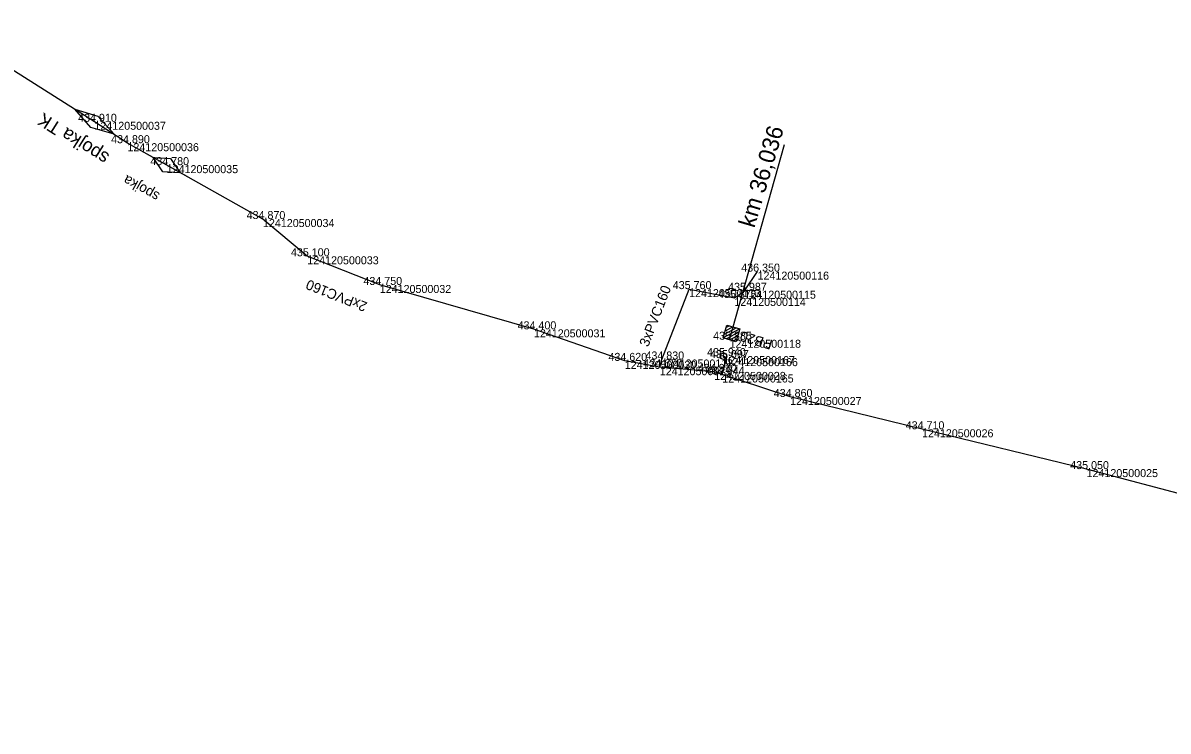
# Model space of a CAD drawing. Extents: x -637342 to -635997, y -1153616 to -1153154.
# Drawn here: x -637177.6 to -637005.8, y -1153373.9 to -1153267.8 of the extents above; entities that cross this region are included whole.
import ezdxf

# ---------------------------------------------------------------- set-up
doc = ezdxf.new("R2010")
doc.units = 0
for name, color, linetype in [('Vrstva 27', 7, 'Continuous'), ('Vrstva 28', 7, 'Continuous'), ('Vrstva 3', 7, 'Continuous'), ('Vrstva 32', 7, 'Continuous'), ('Vrstva 35', 7, 'Continuous'), ('Vrstva 60', 7, 'Continuous'), ('Vrstva 61', 7, 'Continuous')]:
    doc.layers.add(name, color=color, linetype=linetype)

msp = doc.modelspace()

# ---------------------------------------------------------------- linework, layer by layer
at = {"layer": 'Vrstva 27'}
msp.add_line((-637072.5, -1153317.66), (-637072.53, -1153317.76), dxfattribs=at)
msp.add_circle((-637072.52, -1153317.71), 0.5, dxfattribs=at)
at = {"layer": 'Vrstva 28'}
for p, q in [((-637152.95, -1153290.79), (-637159.05, -1153287.39)), ((-637156.57, -1153290.11), (-637158.03, -1153287.95)), ((-637158.03, -1153287.95), (-637155.43, -1153288.07)), ((-637155.43, -1153288.07), (-637153.97, -1153290.23)), ((-637153.97, -1153290.23), (-637156.57, -1153290.11))]:
    msp.add_line(p, q, dxfattribs=at)
for points in [[(-637087.31, -1153318.43), (-637100.93, -1153313.7), (-637124.05, -1153307.05), (-637134.92, -1153302.75), (-637141.56, -1153297.17), (-637156, -1153289.09), (-637161.88, -1153285.8), (-637166.83, -1153282.59), (-637190.3, -1153267.77)], [(-637082.06, -1153319.38), (-637081.76, -1153318.22), (-637077.67, -1153307.67), (-637070.88, -1153309), (-637069.37, -1153307.92), (-637067.4, -1153305.05)], [(-636859.31, -1153373.92), (-636867.59, -1153372.08), (-636889.87, -1153366.37), (-636896.7, -1153364.96), (-636901.09, -1153364.51), (-636913.66, -1153361.72), (-636934.13, -1153356.93), (-636945.13, -1153353.88), (-636947.14, -1153353.6), (-636955.43, -1153351.19), (-636972.02, -1153347.13), (-636986.79, -1153342.81), (-637001.85, -1153338.97), (-637018.07, -1153334.65), (-637042.74, -1153328.68), (-637062.52, -1153323.84), (-637073.89, -1153320.08), (-637082.06, -1153319.38), (-637087.31, -1153318.43)], [(-637072.7, -1153320.47), (-637072.07, -1153318.02), (-637072.52, -1153317.71)]]:
    msp.add_lwpolyline(points, dxfattribs=at)
at = {"layer": 'Vrstva 3'}
for p, q in [((-637071.6, -1153315.26), (-637063.36, -1153285.98)), ((-637070.07, -1153313.63), (-637072.56, -1153314.97)), ((-637070.58, -1153313.48), (-637072.41, -1153314.47)), ((-637071.09, -1153313.33), (-637072.26, -1153313.96)), ((-637071.6, -1153313.17), (-637072.11, -1153313.45)), ((-637070.22, -1153314.14), (-637072.05, -1153315.13)), ((-637070.37, -1153314.65), (-637071.54, -1153315.28)), ((-637070.53, -1153315.15), (-637071.03, -1153315.43))]:
    msp.add_line(p, q, dxfattribs=at)
msp.add_lwpolyline([(-637070.64, -1153315.55), (-637072.56, -1153314.97), (-637071.99, -1153313.06), (-637070.07, -1153313.63)], close=True, dxfattribs=at)
at = {"layer": 'Vrstva 32'}
msp.add_lwpolyline([(-637169.79, -1153280.72), (-637166.3, -1153281.74), (-637163.87, -1153284.46), (-637167.36, -1153283.44), (-637169.79, -1153280.72)], dxfattribs=at)
at = {"layer": 'Vrstva 35'}
for p, q in [((-637124.05, -1153307.05), (-637134.92, -1153302.75)), ((-637081.76, -1153318.22), (-637077.67, -1153307.67))]:
    msp.add_line(p, q, dxfattribs=at)
at = {"layer": 'Vrstva 60'}
for p, q in [((-637166.83, -1153282.59), (-637166.83, -1153282.59)), ((-637161.88, -1153285.8), (-637161.88, -1153285.8)), ((-637156, -1153289.09), (-637156, -1153289.09)), ((-637141.56, -1153297.17), (-637141.56, -1153297.17)), ((-637134.92, -1153302.75), (-637134.92, -1153302.75)), ((-637067.4, -1153305.05), (-637067.4, -1153305.05)), ((-637124.05, -1153307.05), (-637124.05, -1153307.05)), ((-637077.67, -1153307.67), (-637077.67, -1153307.67)), ((-637069.37, -1153307.92), (-637069.37, -1153307.92)), ((-637070.88, -1153309), (-637070.88, -1153309)), ((-637100.93, -1153313.7), (-637100.93, -1153313.7)), ((-637071.6, -1153315.26), (-637071.6, -1153315.26)), ((-637087.31, -1153318.43), (-637087.31, -1153318.43)), ((-637081.76, -1153318.22), (-637081.76, -1153318.22)), ((-637072.52, -1153317.71), (-637072.52, -1153317.71)), ((-637072.07, -1153318.02), (-637072.07, -1153318.02)), ((-637082.06, -1153319.38), (-637082.06, -1153319.38)), ((-637073.89, -1153320.08), (-637073.89, -1153320.08)), ((-637072.7, -1153320.47), (-637072.7, -1153320.47)), ((-637062.52, -1153323.84), (-637062.52, -1153323.84)), ((-637042.74, -1153328.68), (-637042.74, -1153328.68)), ((-637018.07, -1153334.65), (-637018.07, -1153334.65))]:
    msp.add_line(p, q, dxfattribs=at)

# ---------------------------------------------------------------- texts
at = {"layer": 'Vrstva 28'}
msp.add_text('spojka', height=1.5, rotation=150.7705, dxfattribs=at).set_placement((-637156.92, -1153293.35))
at = {"layer": 'Vrstva 3'}
for s, height, rotation, p in [('km 36,036', 2.5, 73.424, (-637067.89, -1153298.61)), ('PB20', 1.5, 163.424, (-637065.05, -1153315.34))]:
    msp.add_text(s, height=height, rotation=rotation, dxfattribs=at).set_placement(p)
at = {"layer": 'Vrstva 32'}
msp.add_text('spojka TK', height=2, rotation=147.7299, dxfattribs=at).set_placement((-637164.45, -1153287.51))
at = {"layer": 'Vrstva 35'}
for s, rotation, p in [('2xPVC160', 158.417, (-637125.81, -1153309.72)), ('3xPVC160', 68.8098, (-637083.8, -1153316.43))]:
    msp.add_text(s, height=1.5, rotation=rotation, dxfattribs=at).set_placement(p)
at = {"layer": 'Vrstva 60'}
for s, p in [('124120500037', (-637166.83, -1153283.79)), ('124120500036', (-637161.88, -1153287)), ('124120500035', (-637156, -1153290.29)), ('124120500034', (-637141.56, -1153298.37)), ('124120500033', (-637134.92, -1153303.95)), ('124120500116', (-637067.4, -1153306.25)), ('124120500032', (-637124.05, -1153308.25)), ('124120500113', (-637077.67, -1153308.87)), ('124120500115', (-637069.37, -1153309.11)), ('124120500114', (-637070.88, -1153310.2)), ('124120500031', (-637100.93, -1153314.9)), ('124120500118', (-637071.6, -1153316.46)), ('124120500030', (-637087.31, -1153319.63)), ('124120500112', (-637081.76, -1153319.42)), ('124120500167', (-637072.52, -1153318.91)), ('124120500166', (-637072.07, -1153319.22)), ('124120500029', (-637082.06, -1153320.58)), ('124120500028', (-637073.89, -1153321.28)), ('124120500165', (-637072.7, -1153321.67)), ('124120500027', (-637062.52, -1153325.04)), ('124120500026', (-637042.74, -1153329.88)), ('124120500025', (-637018.07, -1153335.85))]:
    msp.add_text(s, height=1.2, dxfattribs=at).set_placement(p)
at = {"layer": 'Vrstva 61'}
for s, p in [('434.910', (-637169.28, -1153282.59)), ('434.890', (-637164.33, -1153285.8)), ('434.780', (-637158.45, -1153289.09)), ('434.870', (-637144.01, -1153297.17)), ('435.100', (-637137.37, -1153302.75)), ('436.350', (-637069.85, -1153305.05)), ('434.750', (-637126.5, -1153307.05)), ('435.760', (-637080.12, -1153307.67)), ('435.987', (-637071.82, -1153307.92)), ('435.875', (-637073.33, -1153309)), ('434.400', (-637103.38, -1153313.7)), ('435.885', (-637074.06, -1153315.26)), ('434.620', (-637089.76, -1153318.43)), ('434.830', (-637084.21, -1153318.22)), ('435.940', (-637074.97, -1153317.71)), ('435.097', (-637074.52, -1153318.02)), ('434.670', (-637084.51, -1153319.38)), ('434.910', (-637076.34, -1153320.08)), ('434.644', (-637075.15, -1153320.47)), ('434.860', (-637064.97, -1153323.84)), ('434.710', (-637045.19, -1153328.68)), ('435.050', (-637020.52, -1153334.65))]:
    msp.add_text(s, height=1.2, dxfattribs=at).set_placement(p)

doc.saveas('drawing.dxf')
